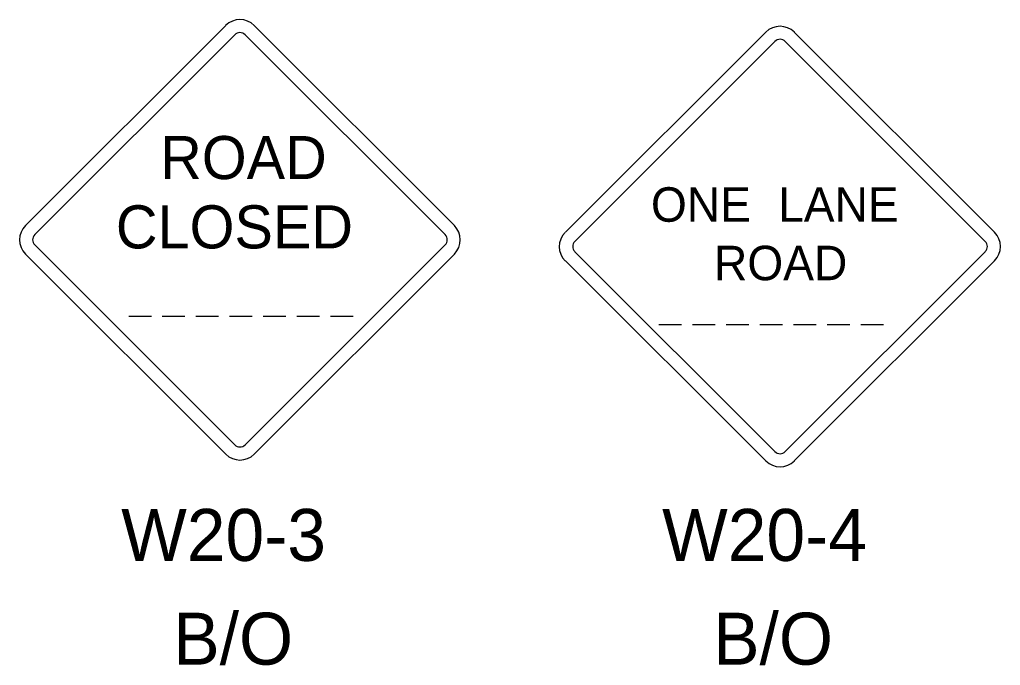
# Model space of a CAD drawing. Extents: x 10034 to 10794, y 10044 to 10499.
# Drawn here: x 10034.9 to 10100.9, y 10206.6 to 10250.1 of the extents above; entities that cross this region are included whole.
import ezdxf

# ---------------------------------------------------------------- set-up
doc = ezdxf.new("R2010")
doc.units = 0
for name, color, linetype in [('DSText', 7, 'Continuous'), ('DSTitle', 7, 'Continuous'), ('PlotBorder_dp', 7, 'Continuous')]:
    doc.layers.add(name, color=color, linetype=linetype)

msp = doc.modelspace()

# ---------------------------------------------------------------- linework, layer by layer
at = {"layer": 'DSText'}
for p, q in [((10035.251, 10236.199), (10048.728, 10249.674)), ((10050.642, 10249.674), (10064.117, 10236.199)), ((10071.602, 10235.749), (10085.078, 10249.223)), ((10086.993, 10249.223), (10100.467, 10235.749)), ((10048.728, 10220.81), (10035.251, 10234.285)), ((10064.117, 10234.285), (10050.642, 10220.81)), ((10085.078, 10220.358), (10071.602, 10233.833)), ((10100.467, 10233.833), (10086.993, 10220.358)), ((10042.195, 10230.111), (10043.722, 10230.111)), ((10044.46, 10230.111), (10045.986, 10230.111)), ((10046.725, 10230.111), (10048.251, 10230.111)), ((10048.989, 10230.111), (10050.516, 10230.111)), ((10051.254, 10230.111), (10052.78, 10230.111)), ((10053.518, 10230.111), (10055.045, 10230.111)), ((10055.783, 10230.111), (10057.309, 10230.111)), ((10077.876, 10229.543), (10079.403, 10229.543)), ((10080.141, 10229.543), (10081.667, 10229.543)), ((10082.406, 10229.543), (10083.932, 10229.543)), ((10084.67, 10229.543), (10086.197, 10229.543)), ((10086.935, 10229.543), (10088.461, 10229.543)), ((10089.2, 10229.543), (10090.726, 10229.543)), ((10091.464, 10229.543), (10092.991, 10229.543))]:
    msp.add_line(p, q, dxfattribs=at)
for centre, start, end in [((10049.683, 10248.712), 45, 135), ((10086.034, 10248.261), 45, 135), ((10036.214, 10235.243), 135, 225), ((10063.153, 10235.243), 315, 45), ((10072.529, 10234.776), 135, 225), ((10099.503, 10234.792), 315, 45), ((10049.687, 10221.771), 225, 315), ((10086.037, 10221.32), 225, 315)]:
    msp.add_arc(centre, 1.358, start, end, dxfattribs=at)
at = {"layer": 'DSTitle'}
for p, q in [((10035.878, 10235.59), (10049.337, 10249.048)), ((10050.033, 10249.048), (10063.491, 10235.59)), ((10072.228, 10235.139), (10085.687, 10248.596)), ((10086.383, 10248.596), (10099.841, 10235.139)), ((10049.337, 10221.436), (10035.878, 10234.894)), ((10063.491, 10234.894), (10050.033, 10221.436)), ((10085.687, 10220.985), (10072.228, 10234.443)), ((10099.841, 10234.443), (10086.383, 10220.985))]:
    msp.add_line(p, q, dxfattribs=at)
for centre, start, end in [((10049.683, 10248.704), 45, 135), ((10086.034, 10248.252), 45, 135), ((10036.223, 10235.243), 135, 225), ((10063.144, 10235.243), 315, 45), ((10072.573, 10234.792), 135, 225), ((10099.495, 10234.792), 315, 45), ((10049.683, 10221.782), 225, 315), ((10086.034, 10221.331), 225, 315)]:
    msp.add_arc(centre, 0.49, start, end, dxfattribs=at)

# ---------------------------------------------------------------- texts
at = {"layer": 'PlotBorder_dp'}
for s, height, p in [('ROAD', 2.901, (10044.317, 10239.33)), ('ONE', 2.3213, (10077.344, 10236.458)), ('LANE', 2.3213, (10085.905, 10236.458)), ('CLOSED', 2.9021, (10041.334, 10234.663)), ('ROAD', 2.3213, (10081.589, 10232.52)), ('W20-3', 3.5, (10041.69, 10213.62)), ('W20-4', 3.5, (10078.095, 10213.62)), ('B/O', 3.5, (10045.199, 10206.634)), ('B/O', 3.5, (10081.532, 10206.634))]:
    msp.add_text(s, height=height, dxfattribs=at).set_placement(p)

doc.saveas('drawing.dxf')
